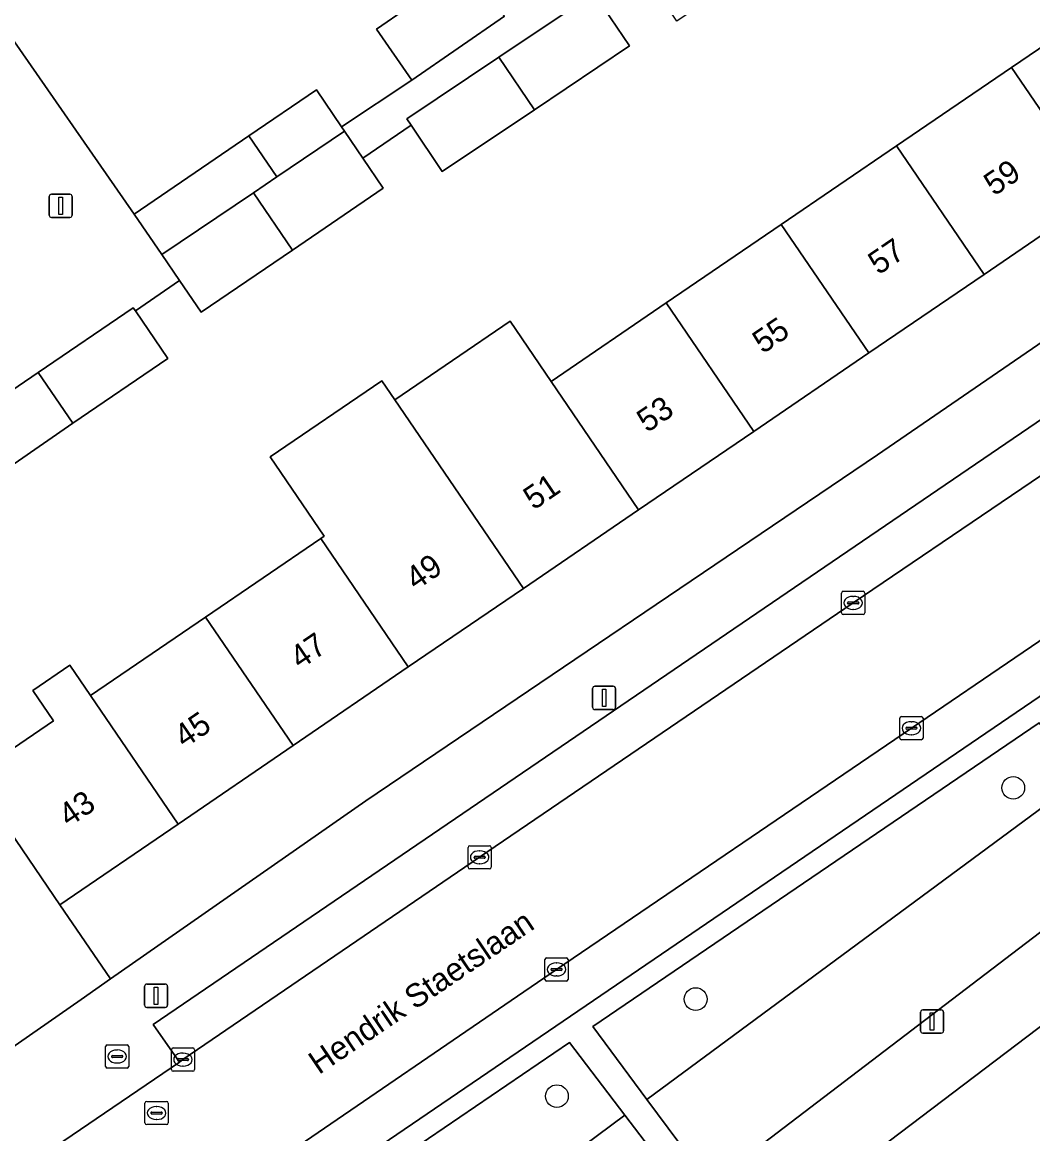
# Model space of a CAD drawing. Extents: x 160030 to 160839, y 385325 to 386450.
# Drawn here: x 160199.85 to 160243.36, y 385935.27 to 385983.11 of the extents above; entities that cross this region are included whole.
import ezdxf

# ---------------------------------------------------------------- set-up
doc = ezdxf.new("R2010")
doc.units = 0
for name, color, linetype in [('IMGEO_Boom', 7, 'Continuous'), ('IMGEO_Erf', 7, 'Continuous'), ('IMGEO_Groenvoorziening', 7, 'Continuous'), ('IMGEO_Kolk', 7, 'Continuous'), ('IMGEO_Lichtmast', 7, 'Continuous'), ('IMGEO_Openbare_ruimte_label', 7, 'Continuous'), ('IMGEO_Pand', 7, 'Continuous'), ('IMGEO_Pand_nummerreeks', 7, 'Continuous'), ('IMGEO_Parkeervlak_open', 7, 'Continuous'), ('IMGEO_Rijbaan_lokaal_open', 7, 'Continuous'), ('IMGEO_Rioolput', 7, 'Continuous'), ('IMGEO_Voetpad_open', 7, 'Continuous')]:
    doc.layers.add(name, color=color, linetype=linetype)

msp = doc.modelspace()

# ---------------------------------------------------------------- linework, layer by layer
at = {"layer": 'IMGEO_Boom'}
for centre in [(160242.519, 385950.155), (160228.842, 385941.061), (160222.869, 385936.885)]:
    msp.add_circle(centre, 0.489, dxfattribs=at)
at = {"layer": 'IMGEO_Erf'}
for points in [[(160199.027, 385982.972), (160204.67, 385974.849), (160209.607, 385978.215), (160212.511, 385980.195), (160213.59, 385978.612), (160216.624, 385980.613), (160215.106, 385982.809), (160219.105, 385985.574), (160223.03, 385988.286), (160224.548, 385986.091), (160226.471, 385987.468), (160225.041, 385989.537), (160229.036, 385992.298), (160233.135, 385995.131), (160234.565, 385993.062), (160234.764, 385992.774), (160236.483, 385994.087), (160234.956, 385996.297), (160238.946, 385999.054)], [(160246.012, 385995.331), (160241.945, 385992.605), (160237.941, 385989.92), (160236.368, 385992.267), (160234.524, 385990.918), (160236.097, 385988.571), (160232.019, 385985.837), (160228.026, 385983.16), (160226.505, 385985.43), (160224.636, 385984.122), (160225.998, 385982.089), (160221.904, 385979.344), (160217.927, 385976.678), (160216.59, 385978.673), (160214.518, 385977.25), (160215.393, 385975.966), (160211.483, 385973.302), (160207.552, 385970.622), (160206.614, 385971.998), (160204.719, 385970.679), (160206.116, 385968.631), (160202.026, 385965.844), (160198.223, 385963.221)], [(160232.531, 385974.406), (160237.488, 385977.785), (160242.446, 385981.165), (160247.403, 385984.545)], [(160246.217, 385975.634), (160241.259, 385972.254), (160236.301, 385968.875), (160231.345, 385965.496), (160226.387, 385962.116), (160221.429, 385958.736), (160216.471, 385955.356), (160211.514, 385951.976), (160206.556, 385948.596), (160201.466, 385945.126), (160203.647, 385941.929), (160214.635, 385949.59), (160236.67, 385964.494), (160247.282, 385971.758)], [(160197.695, 385950.657), (160201.194, 385953.043), (160200.303, 385954.351), (160201.893, 385955.435), (160202.785, 385954.127), (160207.743, 385957.507), (160212.701, 385960.887), (160212.844, 385960.984), (160210.517, 385964.397), (160215.331, 385967.68), (160215.894, 385966.854), (160220.852, 385970.234), (160222.616, 385967.646), (160227.574, 385971.026), (160232.531, 385974.406)], [(160243.707, 385933.638), (160248.496, 385937.268), (160253.287, 385940.898), (160258.076, 385944.528), (160262.944, 385948.218), (160259.939, 385952.187), (160193.53, 385901.886)]]:
    msp.add_lwpolyline(points, dxfattribs=at)
at = {"layer": 'IMGEO_Groenvoorziening'}
for points in [[(160245.461, 385950.551), (160243.628, 385952.959), (160224.419, 385939.879), (160226.741, 385936.743)], [(160247.991, 385947.227), (160245.461, 385950.551), (160226.741, 385936.743), (160229.446, 385933.089)], [(160225.794, 385936.069), (160223.408, 385939.191), (160211.948, 385931.393), (160212.117, 385931.145), (160205.573, 385926.677), (160208.311, 385923.062)], [(160228.569, 385932.436), (160225.794, 385936.069), (160208.311, 385923.062), (160211.216, 385919.226)]]:
    msp.add_lwpolyline(points, close=True, dxfattribs=at)
at = {"layer": 'IMGEO_Kolk'}
for p, q in [((160235.125, 385957.688), (160235.125, 385958.54)), ((160235.2, 385958.614), (160236.052, 385958.614)), ((160235.613, 385958.394), (160235.638, 385958.394)), ((160236.126, 385958.54), (160236.126, 385957.688)), ((160235.384, 385958.108), (160235.384, 385958.12)), ((160235.822, 385958.071), (160235.424, 385958.071)), ((160235.427, 385958.157), (160235.825, 385958.157)), ((160235.636, 385957.834), (160235.611, 385957.834)), ((160235.868, 385958.12), (160235.868, 385958.108)), ((160236.052, 385957.614), (160235.2, 385957.614)), ((160237.631, 385952.296), (160237.631, 385953.148)), ((160237.706, 385953.222), (160238.558, 385953.222)), ((160238.119, 385953.002), (160238.144, 385953.002)), ((160238.632, 385953.148), (160238.632, 385952.296)), ((160237.89, 385952.716), (160237.89, 385952.728)), ((160238.328, 385952.679), (160237.93, 385952.679)), ((160237.933, 385952.765), (160238.331, 385952.765)), ((160238.374, 385952.728), (160238.374, 385952.716)), ((160238.558, 385952.222), (160237.706, 385952.222)), ((160238.142, 385952.442), (160238.117, 385952.442)), ((160219.041, 385946.739), (160219.041, 385947.591)), ((160219.116, 385947.665), (160219.968, 385947.665)), ((160219.529, 385947.445), (160219.554, 385947.445)), ((160220.042, 385947.591), (160220.042, 385946.739)), ((160219.3, 385947.159), (160219.3, 385947.171)), ((160219.738, 385947.122), (160219.34, 385947.122)), ((160219.343, 385947.208), (160219.741, 385947.208)), ((160219.552, 385946.885), (160219.527, 385946.885)), ((160219.784, 385947.171), (160219.784, 385947.159)), ((160219.968, 385946.665), (160219.116, 385946.665)), ((160222.352, 385941.91), (160222.352, 385942.762)), ((160222.427, 385942.836), (160223.279, 385942.836)), ((160222.84, 385942.616), (160222.865, 385942.616)), ((160223.353, 385942.762), (160223.353, 385941.91)), ((160222.611, 385942.33), (160222.611, 385942.342)), ((160223.049, 385942.293), (160222.651, 385942.293)), ((160222.654, 385942.379), (160223.052, 385942.379)), ((160222.863, 385942.056), (160222.838, 385942.056)), ((160223.095, 385942.342), (160223.095, 385942.33)), ((160223.279, 385941.836), (160222.427, 385941.836)), ((160206.267, 385938.031), (160206.267, 385938.883)), ((160206.342, 385938.957), (160207.194, 385938.957)), ((160206.755, 385938.737), (160206.78, 385938.737)), ((160207.268, 385938.883), (160207.268, 385938.031)), ((160206.526, 385938.451), (160206.526, 385938.463)), ((160206.964, 385938.414), (160206.566, 385938.414)), ((160206.569, 385938.5), (160206.967, 385938.5)), ((160206.778, 385938.177), (160206.753, 385938.177)), ((160207.01, 385938.463), (160207.01, 385938.451)), ((160207.194, 385937.957), (160206.342, 385937.957))]:
    msp.add_line(p, q, dxfattribs=at)
for points in [[(160235.125, 385957.688), (160235.125, 385958.54)], [(160235.2, 385958.614), (160236.052, 385958.614)], [(160236.126, 385958.54), (160236.126, 385957.688)], [(160236.052, 385957.614), (160235.2, 385957.614)], [(160237.631, 385952.296), (160237.631, 385953.148)], [(160237.706, 385953.222), (160238.558, 385953.222)], [(160238.632, 385953.148), (160238.632, 385952.296)], [(160238.558, 385952.222), (160237.706, 385952.222)], [(160219.041, 385946.739), (160219.041, 385947.591)], [(160219.116, 385947.665), (160219.968, 385947.665)], [(160220.042, 385947.591), (160220.042, 385946.739)], [(160219.968, 385946.665), (160219.116, 385946.665)], [(160222.352, 385941.91), (160222.352, 385942.762)], [(160222.427, 385942.836), (160223.279, 385942.836)], [(160223.353, 385942.762), (160223.353, 385941.91)], [(160223.279, 385941.836), (160222.427, 385941.836)], [(160206.267, 385938.031), (160206.267, 385938.883)], [(160206.342, 385938.957), (160207.194, 385938.957)], [(160207.268, 385938.883), (160207.268, 385938.031)], [(160207.194, 385937.957), (160206.342, 385937.957)]]:
    msp.add_lwpolyline(points, dxfattribs=at)
for centre, radius, start, end in [((160235.202, 385958.538), 0.0765, 91.552, 178.448), ((160235.202, 385958.538), 0.0765, 91.552, 178.448), ((160236.05, 385958.538), 0.0765, 1.552, 88.448), ((160236.05, 385958.538), 0.0765, 1.552, 88.448), ((160235.424, 385958.117), 0.0403, 85.8775, 175.7526), ((160235.421, 385958.107), 0.0366, 178.938, 274.7102), ((160235.825, 385958.114), 0.043, 264.8664, 352.4533), ((160235.829, 385958.119), 0.0386, 1.7309, 96.639), ((160235.202, 385957.69), 0.0765, 181.552, 268.448), ((160235.202, 385957.69), 0.0765, 181.552, 268.448), ((160236.05, 385957.69), 0.0765, 271.552, 358.448), ((160236.05, 385957.69), 0.0765, 271.552, 358.448), ((160237.708, 385953.146), 0.0765, 91.552, 178.448), ((160237.708, 385953.146), 0.0765, 91.552, 178.448), ((160238.556, 385953.146), 0.0765, 1.552, 88.448), ((160238.556, 385953.146), 0.0765, 1.552, 88.448), ((160237.93, 385952.725), 0.0403, 85.8775, 175.7526), ((160237.927, 385952.715), 0.0366, 178.938, 274.7102), ((160238.331, 385952.722), 0.043, 264.8664, 352.4533), ((160238.335, 385952.727), 0.0386, 1.7309, 96.639), ((160237.708, 385952.298), 0.0765, 181.552, 268.448), ((160237.708, 385952.298), 0.0765, 181.552, 268.448), ((160238.556, 385952.298), 0.0765, 271.552, 358.448), ((160238.556, 385952.298), 0.0765, 271.552, 358.448), ((160219.118, 385947.589), 0.0765, 91.552, 178.448), ((160219.118, 385947.589), 0.0765, 91.552, 178.448), ((160219.966, 385947.589), 0.0765, 1.552, 88.448), ((160219.966, 385947.589), 0.0765, 1.552, 88.448), ((160219.118, 385946.741), 0.0765, 181.552, 268.448), ((160219.118, 385946.741), 0.0765, 181.552, 268.448), ((160219.34, 385947.168), 0.0403, 85.8775, 175.7526), ((160219.337, 385947.158), 0.0366, 178.938, 274.7102), ((160219.741, 385947.165), 0.043, 264.8664, 352.4533), ((160219.745, 385947.17), 0.0386, 1.7309, 96.639), ((160219.966, 385946.741), 0.0765, 271.552, 358.448), ((160219.966, 385946.741), 0.0765, 271.552, 358.448), ((160222.429, 385942.76), 0.0765, 91.552, 178.448), ((160222.429, 385942.76), 0.0765, 91.552, 178.448), ((160223.277, 385942.76), 0.0765, 1.552, 88.448), ((160223.277, 385942.76), 0.0765, 1.552, 88.448), ((160222.651, 385942.339), 0.0403, 85.8775, 175.7526), ((160222.648, 385942.329), 0.0366, 178.938, 274.7102), ((160223.052, 385942.336), 0.043, 264.8664, 352.4533), ((160223.056, 385942.341), 0.0386, 1.7309, 96.639), ((160222.429, 385941.912), 0.0765, 181.552, 268.448), ((160222.429, 385941.912), 0.0765, 181.552, 268.448), ((160223.277, 385941.912), 0.0765, 271.552, 358.448), ((160223.277, 385941.912), 0.0765, 271.552, 358.448), ((160206.344, 385938.881), 0.0765, 91.552, 178.448), ((160206.344, 385938.881), 0.0765, 91.552, 178.448), ((160207.192, 385938.881), 0.0765, 1.552, 88.448), ((160207.192, 385938.881), 0.0765, 1.552, 88.448), ((160206.566, 385938.46), 0.0403, 85.8775, 175.7526), ((160206.563, 385938.45), 0.0366, 178.938, 274.7102), ((160206.967, 385938.457), 0.043, 264.8664, 352.4533), ((160206.971, 385938.462), 0.0386, 1.7309, 96.639), ((160206.344, 385938.033), 0.0765, 181.552, 268.448), ((160206.344, 385938.033), 0.0765, 181.552, 268.448), ((160207.192, 385938.033), 0.0765, 271.552, 358.448), ((160207.192, 385938.033), 0.0765, 271.552, 358.448)]:
    msp.add_arc(centre, radius, start, end, dxfattribs=at)
for centre, major_axis, ratio, start_param, end_param in [((160235.612, 385958.114), (-0.387, 0.002), 0.722429, 4.712389, 7.853982), ((160235.637, 385958.114), (-0.39, 0.002), 0.717154, 1.570796, 4.712389), ((160238.118, 385952.722), (-0.387, 0.002), 0.722429, 4.712389, 7.853982), ((160238.143, 385952.722), (-0.39, 0.002), 0.717154, 1.570796, 4.712389), ((160219.528, 385947.165), (-0.387, 0.002), 0.722429, 4.712389, 7.853982), ((160219.553, 385947.165), (-0.39, 0.002), 0.717154, 1.570796, 4.712389), ((160222.839, 385942.336), (-0.387, 0.002), 0.722429, 4.712389, 7.853982), ((160222.864, 385942.336), (-0.39, 0.002), 0.717154, 1.570796, 4.712389), ((160206.754, 385938.457), (-0.387, 0.002), 0.722429, 4.712389, 7.853982), ((160206.779, 385938.457), (-0.39, 0.002), 0.717154, 1.570796, 4.712389)]:
    msp.add_ellipse(centre, major_axis=major_axis, ratio=ratio, start_param=start_param, end_param=end_param, dxfattribs=at)
at = {"layer": 'IMGEO_Lichtmast'}
for p, q in [((160201.006, 385974.805), (160201.006, 385975.605)), ((160201.006, 385975.605), (160201.006, 385974.805)), ((160201.106, 385975.705), (160201.896, 385975.705)), ((160201.896, 385975.705), (160201.106, 385975.705)), ((160201.996, 385975.605), (160201.996, 385974.805)), ((160201.996, 385974.805), (160201.996, 385975.605)), ((160201.896, 385974.705), (160201.106, 385974.705)), ((160201.106, 385974.705), (160201.896, 385974.705)), ((160224.405, 385953.625), (160224.405, 385954.425)), ((160224.405, 385954.425), (160224.405, 385953.625)), ((160224.505, 385954.525), (160225.295, 385954.525)), ((160225.295, 385954.525), (160224.505, 385954.525)), ((160225.395, 385954.425), (160225.395, 385953.625)), ((160225.395, 385953.625), (160225.395, 385954.425)), ((160225.295, 385953.525), (160224.505, 385953.525)), ((160224.505, 385953.525), (160225.295, 385953.525)), ((160205.113, 385940.806), (160205.113, 385941.606)), ((160205.113, 385941.606), (160205.113, 385940.806)), ((160205.213, 385941.706), (160206.003, 385941.706)), ((160206.003, 385941.706), (160205.213, 385941.706)), ((160206.103, 385941.606), (160206.103, 385940.806)), ((160206.103, 385940.806), (160206.103, 385941.606)), ((160206.003, 385940.706), (160205.213, 385940.706)), ((160205.213, 385940.706), (160206.003, 385940.706)), ((160238.626, 385940.595), (160239.416, 385940.595)), ((160239.416, 385940.595), (160238.626, 385940.595)), ((160238.526, 385939.695), (160238.526, 385940.495)), ((160238.526, 385940.495), (160238.526, 385939.695)), ((160239.516, 385940.495), (160239.516, 385939.695)), ((160239.516, 385939.695), (160239.516, 385940.495)), ((160239.416, 385939.595), (160238.626, 385939.595)), ((160238.626, 385939.595), (160239.416, 385939.595))]:
    msp.add_line(p, q, dxfattribs=at)
for points in [[(160201.426, 385975.58), (160201.576, 385975.58), (160201.576, 385974.83), (160201.426, 385974.83), (160201.426, 385975.58)], [(160224.825, 385954.4), (160224.975, 385954.4), (160224.975, 385953.65), (160224.825, 385953.65), (160224.825, 385954.4)], [(160205.533, 385941.581), (160205.683, 385941.581), (160205.683, 385940.831), (160205.533, 385940.831), (160205.533, 385941.581)], [(160238.946, 385940.47), (160239.096, 385940.47), (160239.096, 385939.72), (160238.946, 385939.72), (160238.946, 385940.47)]]:
    msp.add_lwpolyline(points, dxfattribs=at)
for centre, start, end in [((160201.106, 385975.605), 90, 180), ((160201.106, 385975.605), 90, 180), ((160201.896, 385975.605), 0, 90), ((160201.896, 385975.605), 360, 90), ((160201.106, 385974.805), 180, 270), ((160201.106, 385974.805), 180, 270), ((160201.896, 385974.805), 270, 0), ((160201.896, 385974.805), 270, 0), ((160224.505, 385954.425), 90, 180), ((160224.505, 385954.425), 90, 180), ((160225.295, 385954.425), 0, 90), ((160225.295, 385954.425), 360, 90), ((160224.505, 385953.625), 180, 270), ((160224.505, 385953.625), 180, 270), ((160225.295, 385953.625), 270, 0), ((160225.295, 385953.625), 270, 0), ((160205.213, 385941.606), 90, 180), ((160205.213, 385941.606), 90, 180), ((160206.003, 385941.606), 0, 90), ((160206.003, 385941.606), 360, 90), ((160205.213, 385940.806), 180, 270), ((160205.213, 385940.806), 180, 270), ((160206.003, 385940.806), 270, 0), ((160206.003, 385940.806), 270, 0), ((160238.626, 385940.495), 90, 180), ((160238.626, 385940.495), 90, 180), ((160239.416, 385940.495), 0, 90), ((160239.416, 385940.495), 360, 90), ((160238.626, 385939.695), 180, 270), ((160238.626, 385939.695), 180, 270), ((160239.416, 385939.695), 270, 0), ((160239.416, 385939.695), 270, 0)]:
    msp.add_arc(centre, 0.1, start, end, dxfattribs=at)
at = {"layer": 'IMGEO_Pand'}
for points in [[(160220.609, 385983.368), (160219.105, 385985.574), (160215.106, 385982.809), (160216.624, 385980.613)], [(160246.217, 385975.634), (160251.174, 385979.014), (160247.403, 385984.545), (160242.446, 385981.165)], [(160224.636, 385984.122), (160224.476, 385984.361), (160220.363, 385981.604), (160221.904, 385979.344), (160225.998, 385982.089)], [(160221.904, 385979.344), (160220.363, 385981.604), (160216.404, 385978.951), (160216.59, 385978.673), (160217.927, 385976.678)], [(160242.446, 385981.165), (160237.488, 385977.785), (160241.259, 385972.254), (160246.217, 385975.634)], [(160213.722, 385978.418), (160213.59, 385978.612), (160212.511, 385980.195), (160209.607, 385978.215), (160210.81, 385976.45)], [(160214.518, 385977.25), (160213.722, 385978.418), (160210.81, 385976.45), (160209.801, 385975.769), (160211.483, 385973.302), (160215.393, 385975.966)], [(160209.801, 385975.769), (160210.81, 385976.45), (160209.607, 385978.215), (160204.67, 385974.849), (160205.858, 385973.106)], [(160236.301, 385968.875), (160241.259, 385972.254), (160237.488, 385977.785), (160232.531, 385974.406)], [(160209.801, 385975.769), (160205.858, 385973.106), (160206.614, 385971.998), (160207.552, 385970.622), (160211.483, 385973.302)], [(160232.531, 385974.406), (160227.574, 385971.026), (160231.345, 385965.496), (160236.301, 385968.875)], [(160204.719, 385970.679), (160204.625, 385970.817), (160200.536, 385968.03), (160202.026, 385965.844), (160206.116, 385968.631)], [(160226.387, 385962.116), (160231.345, 385965.496), (160227.574, 385971.026), (160222.616, 385967.646)], [(160222.616, 385967.646), (160220.852, 385970.234), (160215.894, 385966.854), (160221.429, 385958.736), (160226.387, 385962.116)], [(160202.026, 385965.844), (160200.536, 385968.03), (160196.718, 385965.429), (160196.78, 385965.338), (160198.223, 385963.221)], [(160215.894, 385966.854), (160215.331, 385967.68), (160210.517, 385964.397), (160212.844, 385960.984), (160212.701, 385960.887), (160216.471, 385955.356), (160221.429, 385958.736)], [(160211.514, 385951.976), (160216.471, 385955.356), (160212.701, 385960.887), (160207.743, 385957.507)], [(160207.743, 385957.507), (160202.785, 385954.127), (160206.556, 385948.596), (160211.514, 385951.976)], [(160202.785, 385954.127), (160201.893, 385955.435), (160200.303, 385954.351), (160201.194, 385953.043), (160197.695, 385950.657), (160201.466, 385945.126), (160206.556, 385948.596)]]:
    msp.add_lwpolyline(points, close=True, dxfattribs=at)
at = {"layer": 'IMGEO_Parkeervlak_open'}
for points in [[(160251.076, 385968.648), (160266.061, 385978.794), (160264.949, 385980.444), (160262.504, 385978.781), (160248.06, 385968.959), (160205.48, 385939.962), (160206.621, 385938.346), (160206.768, 385938.457), (160219.542, 385947.165), (160235.626, 385958.114), (160249.252, 385967.362)], [(160254.236, 385963.684), (160252.565, 385962.543), (160238.132, 385952.722), (160222.853, 385942.336), (160210.086, 385933.612), (160194.822, 385923.214), (160189.51, 385919.608), (160190.607, 385917.966), (160211.427, 385932.129), (160255.35, 385962.044)]]:
    msp.add_lwpolyline(points, close=True, dxfattribs=at)
at = {"layer": 'IMGEO_Rijbaan_lokaal_open'}
for points in [[(160196.718, 385965.429), (160200.536, 385968.03), (160204.625, 385970.817), (160204.719, 385970.679), (160206.614, 385971.998), (160205.858, 385973.106), (160204.67, 385974.849), (160199.027, 385982.972)], [(160254.236, 385963.684), (160254.392, 385963.771), (160251.076, 385968.648), (160249.252, 385967.362), (160235.626, 385958.114), (160219.542, 385947.165), (160206.768, 385938.457), (160206.621, 385938.346), (160199.125, 385933.25), (160193.787, 385929.654), (160191.502, 385928.056), (160191.296, 385927.917), (160183.75, 385922.776), (160180.114, 385920.297)], [(160183.845, 385915.715), (160189.51, 385919.608), (160194.822, 385923.214), (160210.086, 385933.612), (160222.853, 385942.336), (160238.132, 385952.722), (160252.565, 385962.543), (160254.236, 385963.684)], [(160198.726, 385938.499), (160202.379, 385941.045), (160203.647, 385941.929), (160201.466, 385945.126), (160197.695, 385950.657)]]:
    msp.add_lwpolyline(points, dxfattribs=at)
at = {"layer": 'IMGEO_Rioolput'}
for p, q in [((160203.508, 385939.091), (160204.36, 385939.091)), ((160203.433, 385938.165), (160203.433, 385939.017)), ((160203.735, 385938.634), (160204.133, 385938.634)), ((160203.921, 385938.871), (160203.946, 385938.871)), ((160204.434, 385939.017), (160204.434, 385938.165)), ((160203.692, 385938.585), (160203.692, 385938.597)), ((160204.13, 385938.548), (160203.732, 385938.548)), ((160203.944, 385938.311), (160203.919, 385938.311)), ((160204.176, 385938.597), (160204.176, 385938.585)), ((160204.36, 385938.091), (160203.508, 385938.091)), ((160205.132, 385935.732), (160205.132, 385936.584)), ((160205.207, 385936.658), (160206.059, 385936.658)), ((160205.62, 385936.438), (160205.645, 385936.438)), ((160206.133, 385936.584), (160206.133, 385935.732)), ((160205.391, 385936.152), (160205.391, 385936.164)), ((160205.829, 385936.115), (160205.431, 385936.115)), ((160205.434, 385936.201), (160205.832, 385936.201)), ((160205.643, 385935.878), (160205.618, 385935.878)), ((160205.875, 385936.164), (160205.875, 385936.152)), ((160206.059, 385935.658), (160205.207, 385935.658))]:
    msp.add_line(p, q, dxfattribs=at)
for points in [[(160203.508, 385939.091), (160204.36, 385939.091)], [(160203.433, 385938.165), (160203.433, 385939.017)], [(160204.434, 385939.017), (160204.434, 385938.165)], [(160204.36, 385938.091), (160203.508, 385938.091)], [(160205.132, 385935.732), (160205.132, 385936.584)], [(160205.207, 385936.658), (160206.059, 385936.658)], [(160206.133, 385936.584), (160206.133, 385935.732)], [(160206.059, 385935.658), (160205.207, 385935.658)]]:
    msp.add_lwpolyline(points, dxfattribs=at)
for centre, radius, start, end in [((160203.51, 385939.015), 0.0765, 91.552, 178.448), ((160203.51, 385939.015), 0.0765, 91.552, 178.448), ((160204.358, 385939.015), 0.0765, 1.552, 88.448), ((160204.358, 385939.015), 0.0765, 1.552, 88.448), ((160203.732, 385938.594), 0.0403, 85.8775, 175.7526), ((160204.137, 385938.596), 0.0386, 1.7309, 96.639), ((160203.51, 385938.167), 0.0765, 181.552, 268.448), ((160203.51, 385938.167), 0.0765, 181.552, 268.448), ((160203.729, 385938.584), 0.0366, 178.938, 274.7102), ((160204.133, 385938.591), 0.043, 264.8664, 352.4533), ((160204.358, 385938.167), 0.0765, 271.552, 358.448), ((160204.358, 385938.167), 0.0765, 271.552, 358.448), ((160205.209, 385936.582), 0.0765, 91.552, 178.448), ((160205.209, 385936.582), 0.0765, 91.552, 178.448), ((160206.057, 385936.582), 0.0765, 1.552, 88.448), ((160206.057, 385936.582), 0.0765, 1.552, 88.448), ((160205.209, 385935.734), 0.0765, 181.552, 268.448), ((160205.209, 385935.734), 0.0765, 181.552, 268.448), ((160205.431, 385936.161), 0.0403, 85.8775, 175.7526), ((160205.428, 385936.151), 0.0366, 178.938, 274.7102), ((160205.832, 385936.158), 0.043, 264.8664, 352.4533), ((160205.836, 385936.163), 0.0386, 1.7309, 96.639), ((160206.057, 385935.734), 0.0765, 271.552, 358.448), ((160206.057, 385935.734), 0.0765, 271.552, 358.448)]:
    msp.add_arc(centre, radius, start, end, dxfattribs=at)
for centre, major_axis, ratio, start_param, end_param in [((160203.92, 385938.591), (-0.387, 0.002), 0.722429, 4.712389, 7.853982), ((160203.945, 385938.591), (-0.39, 0.002), 0.717154, 1.570796, 4.712389), ((160205.619, 385936.158), (-0.387, 0.002), 0.722429, 4.712389, 7.853982), ((160205.644, 385936.158), (-0.39, 0.002), 0.717154, 1.570796, 4.712389)]:
    msp.add_ellipse(centre, major_axis=major_axis, ratio=ratio, start_param=start_param, end_param=end_param, dxfattribs=at)
at = {"layer": 'IMGEO_Voetpad_open'}
for points in [[(160220.609, 385983.368), (160216.624, 385980.613), (160213.59, 385978.612), (160213.722, 385978.418), (160214.518, 385977.25), (160216.59, 385978.673), (160216.404, 385978.951), (160220.363, 385981.604), (160224.476, 385984.361)], [(160264.308, 385983.056), (160261.085, 385980.868), (160254.916, 385976.945), (160247.282, 385971.758), (160236.67, 385964.494), (160214.635, 385949.59), (160203.647, 385941.929), (160202.379, 385941.045), (160198.726, 385938.499)], [(160199.125, 385933.25), (160206.621, 385938.346), (160205.48, 385939.962), (160248.06, 385968.959), (160262.504, 385978.781), (160264.949, 385980.444), (160266.061, 385978.794)], [(160256.53, 385965.166), (160254.392, 385963.771), (160254.236, 385963.684), (160255.35, 385962.044), (160211.427, 385932.129), (160190.607, 385917.966), (160189.51, 385919.608), (160183.845, 385915.715), (160187.317, 385914.588), (160188.71, 385915.54), (160203.799, 385925.846), (160203.991, 385925.611), (160204.553, 385925.977), (160207.36, 385922.327), (160210.283, 385918.527), (160191.771, 385904.42), (160193.53, 385901.886), (160259.939, 385952.187)]]:
    msp.add_lwpolyline(points, dxfattribs=at)
for points in [[(160224.419, 385939.879), (160243.628, 385952.959), (160245.461, 385950.551), (160247.991, 385947.227), (160229.446, 385933.089), (160226.741, 385936.743)], [(160225.794, 385936.069), (160228.569, 385932.436), (160211.216, 385919.226), (160208.311, 385923.062), (160205.573, 385926.677), (160212.117, 385931.145), (160211.948, 385931.393), (160223.408, 385939.191)]]:
    msp.add_lwpolyline(points, close=True, dxfattribs=at)

# ---------------------------------------------------------------- texts
at = {"layer": 'IMGEO_Openbare_ruimte_label'}
msp.add_text('Hendrik Staetslaan', height=1, rotation=34.1191, dxfattribs=at).set_placement((160212.621, 385937.789))
at = {"layer": 'IMGEO_Pand_nummerreeks'}
for s, rotation, p in [('59', 34.284, (160241.693, 385975.601)), ('57', 34.284, (160236.713, 385972.206)), ('55', 34.284, (160231.733, 385968.811)), ('53', 34.284, (160226.753, 385965.416)), ('51', 34.2858, (160221.867, 385962.084)), ('49', 34.2858, (160216.793, 385958.626)), ('47', 34.284, (160211.813, 385955.231)), ('45', 34.284, (160206.833, 385951.836)), ('43', 34.2858, (160201.853, 385948.441))]:
    msp.add_text(s, height=1, rotation=rotation, dxfattribs=at).set_placement(p)

doc.saveas('drawing.dxf')
